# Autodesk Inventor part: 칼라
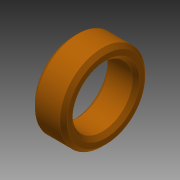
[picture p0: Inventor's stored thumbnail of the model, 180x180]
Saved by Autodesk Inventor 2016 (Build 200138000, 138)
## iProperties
Created: 2016-10
Part Number: 칼라
Material: 강철, 연강
Document SubType Name: Modeling
Designer: mduedu
Density: 1 g/cm^3
Appearance: 주황색
Author: mduedu
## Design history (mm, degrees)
sketch "스케치1"
  geometry: C1 r 12 at (0, 0); C2 r 8.5 at (0, 0); 1 further point
  constraints: 2 centre point, 2 coincident
  dimensions: "d0" = 24 diameter of C1; "d1" = 17 diameter of C2
extrude "돌출1" new body sketch "스케치1" distance "d2" = 9; taper "d3" = 0 deg
chamfer "모따기1" distance "d4" = 1; stored, may be unused: second distance "d5" = 2, angle "d6" = 45 deg
node "솔리드1"
